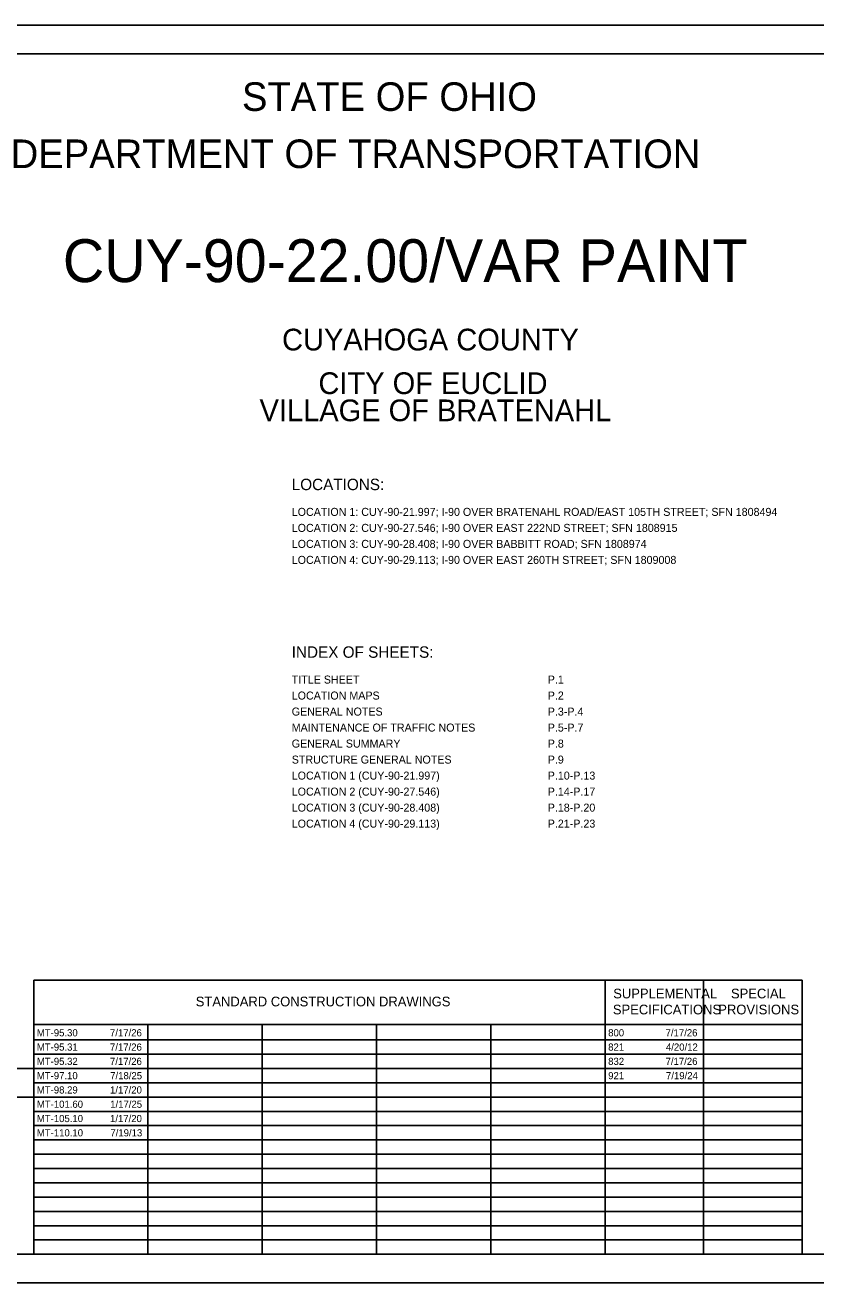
# Model space of a CAD drawing. Extents: x -8.3 to 34, y 0 to 22.
# Drawn here: x 10 to 23.84, y 0 to 22 of the extents above; entities that cross this region are included whole.
import ezdxf

# ---------------------------------------------------------------- set-up
doc = ezdxf.new("R2010")
doc.units = 0
for name, color, linetype in [('SH_Border', 7, 'Continuous'), ('SH_Cut_Line', 7, 'Continuous'), ('SH_Data', 7, 'Continuous'), ('SH_Text', 7, 'Continuous')]:
    doc.layers.add(name, color=color, linetype=linetype)

msp = doc.modelspace()

# ---------------------------------------------------------------- linework, layer by layer
at = {"layer": 'SH_Border'}
msp.add_lwpolyline([(1.5, 21.5), (33.5, 21.5), (33.5, 0.5), (1.5, 0.5)], close=True, dxfattribs=at)
at = {"layer": 'SH_Cut_Line'}
msp.add_lwpolyline([(0, 0), (34, 0), (34, 22), (0, 22)], close=True, dxfattribs=at)
at = {"layer": 'SH_Data'}
for p, q in [((10.15, 5.292), (23.6, 5.292)), ((10.15, 0.5), (10.15, 5.292)), ((20.15, 0.5), (20.15, 5.292)), ((21.875, 0.5), (21.875, 5.292)), ((23.6, 0.5), (23.6, 5.292)), ((10.15, 4.521), (23.6, 4.521)), ((12.15, 0.5), (12.15, 4.521)), ((14.15, 0.5), (14.15, 4.521)), ((16.15, 0.5), (16.15, 4.521)), ((18.15, 0.5), (18.15, 4.521)), ((10.15, 4.25), (23.6, 4.25)), ((10.15, 4), (23.6, 4)), ((7.35, 3.75), (10.15, 3.75)), ((10.15, 3.75), (23.6, 3.75)), ((10.15, 3.5), (23.6, 3.5)), ((7.35, 3.25), (10.15, 3.25)), ((10.15, 3.25), (23.6, 3.25)), ((10.15, 3), (23.6, 3)), ((10.15, 2.75), (23.6, 2.75)), ((10.15, 2.5), (23.6, 2.5)), ((10.15, 2.25), (23.6, 2.25)), ((10.15, 2), (23.6, 2)), ((10.15, 1.75), (23.6, 1.75)), ((10.15, 1.5), (23.6, 1.5)), ((10.15, 1.25), (23.6, 1.25)), ((10.15, 1), (23.6, 1)), ((10.15, 0.75), (23.6, 0.75))]:
    msp.add_line(p, q, dxfattribs=at)

# ---------------------------------------------------------------- texts
for s, p in [('MT-95.30', (10.205, 4.312)), ('7/17/26', (11.485, 4.312)), ('800', (20.205, 4.312)), ('7/17/26', (21.21, 4.312)), ('MT-95.31', (10.205, 4.062)), ('7/17/26', (11.485, 4.062)), ('821', (20.205, 4.062)), ('4/20/12', (21.216, 4.062)), ('MT-95.32', (10.205, 3.812)), ('7/17/26', (11.485, 3.812)), ('832', (20.205, 3.812)), ('7/17/26', (21.21, 3.812)), ('MT-97.10', (10.205, 3.562)), ('7/18/25', (11.489, 3.562)), ('921', (20.205, 3.562)), ('7/19/24', (21.217, 3.562)), ('MT-98.29', (10.205, 3.312)), ('1/17/20', (11.486, 3.312)), ('MT-101.60', (10.205, 3.062)), ('1/17/25', (11.489, 3.062)), ('MT-105.10', (10.205, 2.812)), ('1/17/20', (11.486, 2.812)), ('MT-110.10', (10.205, 2.562)), ('7/19/13', (11.492, 2.562))]:
    msp.add_text(s, height=0.125, dxfattribs=at).set_placement(p)
at = {"layer": 'SH_Text'}
for s, height, p in [('STATE OF OHIO', 0.5, (13.795, 20.5)), ('DEPARTMENT OF TRANSPORTATION', 0.5, (9.747, 19.5)), ('CUY-90-22.00/VAR PAINT', 0.75, (10.66, 17.505)), ('CUYAHOGA COUNTY', 0.38, (14.497, 16.31)), ('CITY OF EUCLID', 0.38, (15.134, 15.547)), ('VILLAGE OF BRATENAHL', 0.38, (14.103, 15.072)), ('LOCATIONS:', 0.2, (14.666, 13.866)), ('LOCATION 1: CUY-90-21.997; I-90 OVER BRATENAHL ROAD/EAST 105TH STREET; SFN 1808494', 0.14, (14.666, 13.416)), ('LOCATION 2: CUY-90-27.546; I-90 OVER EAST 222ND STREET; SFN 1808915', 0.14, (14.666, 13.136)), ('LOCATION 3: CUY-90-28.408; I-90 OVER BABBITT ROAD; SFN 1808974', 0.14, (14.666, 12.856)), ('LOCATION 4: CUY-90-29.113; I-90 OVER EAST 260TH STREET; SFN 1809008', 0.14, (14.666, 12.576)), ('INDEX OF SHEETS:', 0.2, (14.666, 10.934)), ('TITLE SHEET', 0.14, (14.666, 10.483)), ('P.1', 0.14, (19.147, 10.483)), ('LOCATION MAPS', 0.14, (14.666, 10.203)), ('P.2', 0.14, (19.147, 10.203)), ('GENERAL NOTES', 0.14, (14.666, 9.923)), ('P.3-P.4', 0.14, (19.147, 9.923)), ('MAINTENANCE OF TRAFFIC NOTES', 0.14, (14.666, 9.643)), ('P.5-P.7', 0.14, (19.147, 9.643)), ('GENERAL SUMMARY', 0.14, (14.666, 9.363)), ('P.8', 0.14, (19.147, 9.363)), ('STRUCTURE GENERAL NOTES', 0.14, (14.666, 9.083)), ('P.9', 0.14, (19.147, 9.083)), ('LOCATION 1 (CUY-90-21.997)', 0.14, (14.666, 8.803)), ('P.10-P.13', 0.14, (19.147, 8.803)), ('LOCATION 2 (CUY-90-27.546)', 0.14, (14.666, 8.523)), ('P.14-P.17', 0.14, (19.147, 8.523)), ('LOCATION 3 (CUY-90-28.408)', 0.14, (14.666, 8.243)), ('P.18-P.20', 0.14, (19.147, 8.243)), ('LOCATION 4 (CUY-90-29.113)', 0.14, (14.666, 7.963)), ('P.21-P.23', 0.14, (19.147, 7.963)), ('SUPPLEMENTAL', 0.17, (20.293, 4.976)), ('SPECIAL', 0.17, (22.354, 4.976)), ('STANDARD CONSTRUCTION DRAWINGS', 0.17, (12.986, 4.836)), ('SPECIFICATIONS', 0.17, (20.287, 4.696)), ('PROVISIONS', 0.17, (22.132, 4.696))]:
    msp.add_text(s, height=height, dxfattribs=at).set_placement(p)

doc.saveas('drawing.dxf')
